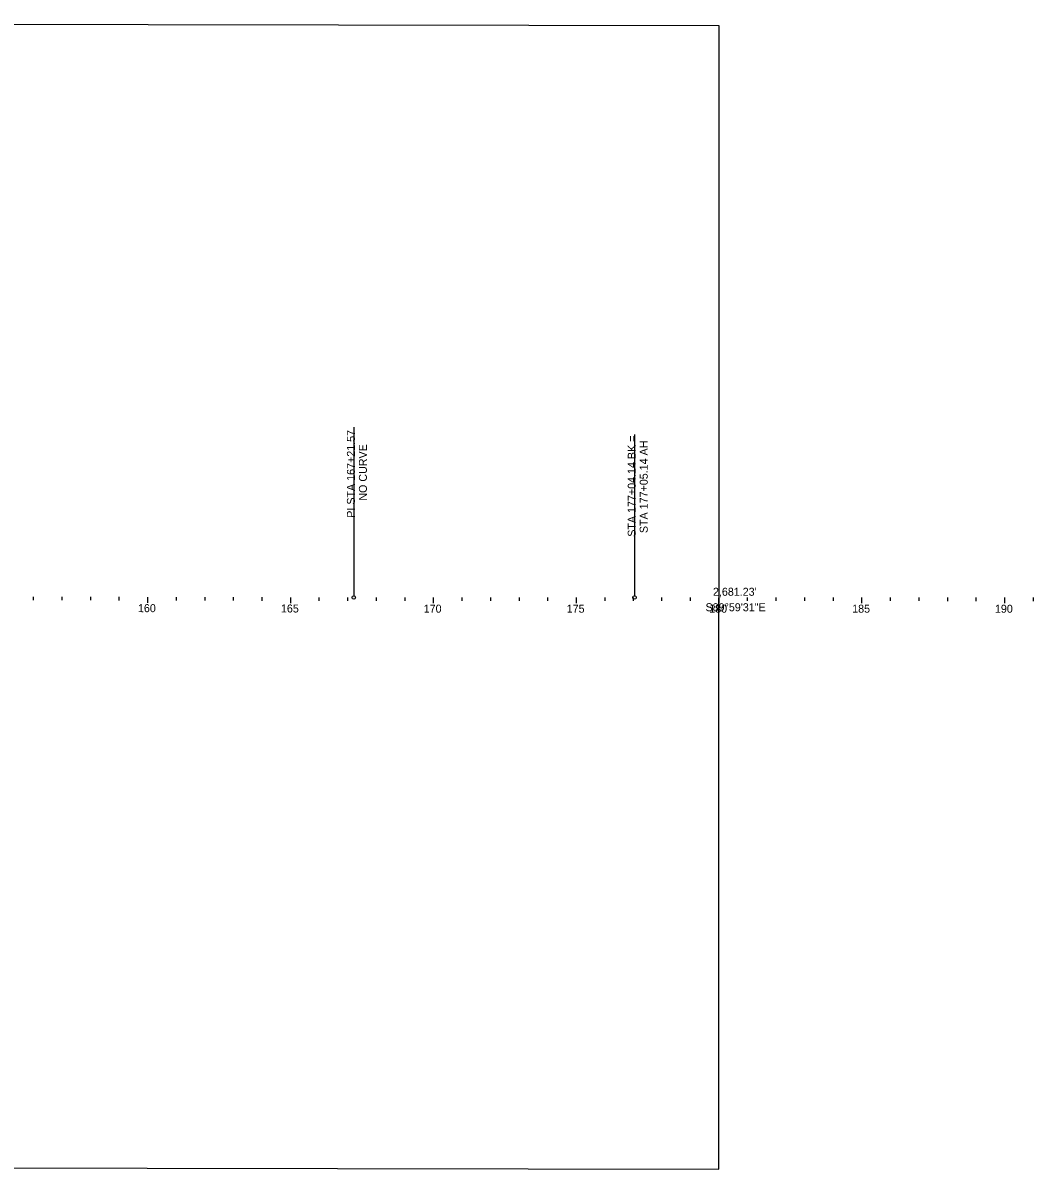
# Model space of a CAD drawing. Extents: x 117326 to 225548, y 573011 to 581051.
# Drawn here: x 133397 to 136932, y 573011 to 577021 of the extents above; entities that cross this region are included whole.
import ezdxf

# ---------------------------------------------------------------- set-up
doc = ezdxf.new("R2010")
doc.units = 0
for name, color, linetype in [('_CIVIL_CONSTRUCTION', 7, 'Continuous'), ('GE_P_Alignment_100_Cardinal_Points', 7, 'Continuous'), ('GE_P_Alignment_100_Curve_Data', 7, 'Continuous'), ('GE_P_Alignment_100_Distances', 7, 'Continuous'), ('SC_Scratch2', 7, 'Continuous')]:
    doc.layers.add(name, color=color, linetype=linetype)

msp = doc.modelspace()

# ---------------------------------------------------------------- linework, layer by layer
at = {"layer": 'GE_P_Alignment_100_Cardinal_Points'}
for p, q in [((134554.6, 575606.5), (134554.5, 575016.8)), ((135537.2, 575580.7), (135537.1, 575016.7))]:
    msp.add_line(p, q, dxfattribs=at)
for centre in [(134554.5, 575010.8), (135537.1, 575010.7)]:
    msp.add_circle(centre, 6, dxfattribs=at)
at = {"layer": 'GE_P_Alignment_100_Curve_Data'}
for p, q in [((133433, 575013.4), (133432.9, 575001.4)), ((133533, 575013.1), (133532.9, 575001.1)), ((133633, 575012.9), (133632.9, 575000.9)), ((133733, 575012.7), (133732.9, 575000.7)), ((133833, 575012.5), (133832.9, 574992.5)), ((133933, 575012.2), (133932.9, 575000.2)), ((134033, 575012), (134032.9, 575000)), ((134133, 575011.8), (134132.9, 574999.8)), ((134233, 575011.6), (134232.9, 574999.6)), ((134333, 575011.3), (134332.9, 574991.3)), ((134432.9, 575011.1), (134432.9, 574999.1)), ((134532.9, 575010.9), (134532.9, 574998.9)), ((134632.9, 575010.8), (134632.9, 574998.8)), ((134732.9, 575010.8), (134732.9, 574998.8)), ((134832.9, 575010.8), (134832.9, 574990.8)), ((134932.9, 575010.8), (134932.9, 574998.8)), ((135032.9, 575010.8), (135032.9, 574998.8)), ((135132.9, 575010.8), (135132.9, 574998.8)), ((135232.9, 575010.7), (135232.9, 574998.7)), ((135332.9, 575010.7), (135332.9, 574990.7)), ((135432.9, 575010.7), (135432.9, 574998.7)), ((135532.9, 575010.7), (135532.9, 574998.7)), ((135631.9, 575010.7), (135631.9, 574998.7)), ((135731.9, 575010.7), (135731.9, 574998.7)), ((135831.9, 575010.7), (135831.9, 574990.7)), ((135931.9, 575010.6), (135931.9, 574998.6)), ((136031.9, 575010.6), (136031.9, 574998.6)), ((136131.9, 575010.6), (136131.9, 574998.6)), ((136231.9, 575010.6), (136231.9, 574998.6)), ((136331.9, 575010.6), (136331.9, 574990.6)), ((136431.9, 575010.6), (136431.9, 574998.6)), ((136531.9, 575010.6), (136531.9, 574998.6)), ((136631.9, 575010.5), (136631.9, 574998.5)), ((136731.9, 575010.5), (136731.9, 574998.5)), ((136831.9, 575010.5), (136831.9, 574990.5)), ((136931.9, 575010.5), (136931.9, 574998.5))]:
    msp.add_line(p, q, dxfattribs=at)
at = {"layer": 'GE_P_Alignment_100_Distances'}
msp.add_lwpolyline([(129837.4, 577021.4), (129828.5, 573021.4), (135832.7, 573010.7), (135833.2, 577010.7)], close=True, dxfattribs=at)
at = {"layer": 'SC_Scratch2'}
msp.add_circle((134554.5, 575010.8), 0.05, dxfattribs=at)

# ---------------------------------------------------------------- texts
at = {"layer": '_CIVIL_CONSTRUCTION'}
msp.add_text('S89°59\'31"E', height=28, rotation=359.9918, dxfattribs=at).set_placement((135785.7, 574962.7))
at = {"layer": 'GE_P_Alignment_100_Cardinal_Points'}
for s, rotation, p in [('PI STA 167+21.57', 89.9918, (134558.7, 575290)), ('NO CURVE', 89.9918, (134600.7, 575349.6)), ('STA 177+04.14 BK =', 89.9918, (135541.4, 575223.4)), ('STA 177+05.14 AH', 89.9918, (135583.4, 575236.2)), ("2,681.23'", 359.9918, (135811.7, 575016.9))]:
    msp.add_text(s, height=28, rotation=rotation, dxfattribs=at).set_placement(p)
at = {"layer": 'GE_P_Alignment_100_Curve_Data'}
for s, rotation, p in [('160', 359.8716, (133799.4, 574959.5)), ('165', 359.8716, (134299.8, 574958.4)), ('170', 359.9918, (134799.5, 574957.8)), ('175', 359.9918, (135299.9, 574957.7)), ('180', 359.9918, (135798.5, 574957.7)), ('185', 359.9918, (136298.9, 574957.6)), ('190', 359.9918, (136798.5, 574957.5))]:
    msp.add_text(s, height=28, rotation=rotation, dxfattribs=at).set_placement(p)

doc.saveas('drawing.dxf')
